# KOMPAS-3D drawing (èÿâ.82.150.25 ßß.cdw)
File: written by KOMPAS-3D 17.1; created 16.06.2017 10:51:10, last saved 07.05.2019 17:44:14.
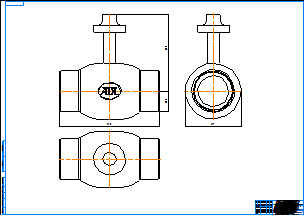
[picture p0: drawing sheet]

Sheet 1: A0, landscape

Title block, sheet 1: name: КШГ.82.150.25 сс; material: Внимание! Данный продукт является объектом авторского права ООО «Торговый Дом АДЛ». / Запрещается изменение, копирование, распространение / (в том числе путем копирования на другие сайты и ресурсы в Интернете) / или любое иное использование информации и объектов без предварительного / согласия правообладателя (ООО «Торговый Дом АДЛ»).; scale: 1:1; sheets: 1; organisation: ООО "Торговый дом АДЛ"; sheet format: A0; stored path: C:\Users\tra\Desktop\2д чертежи\Шаровые краны БИВАЛ\КШ_Бивал_серия_82_85\KOMPAS 2D\КШГ.82.150.25 сс.cdw

Views: Спереди 1, Проекционный вид 2, Проекционный вид 3
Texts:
  Klimkovich
  ADL
Dimensions and other numbers on the sheet: 390; 300; 79,5; 219; 1:1; 1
